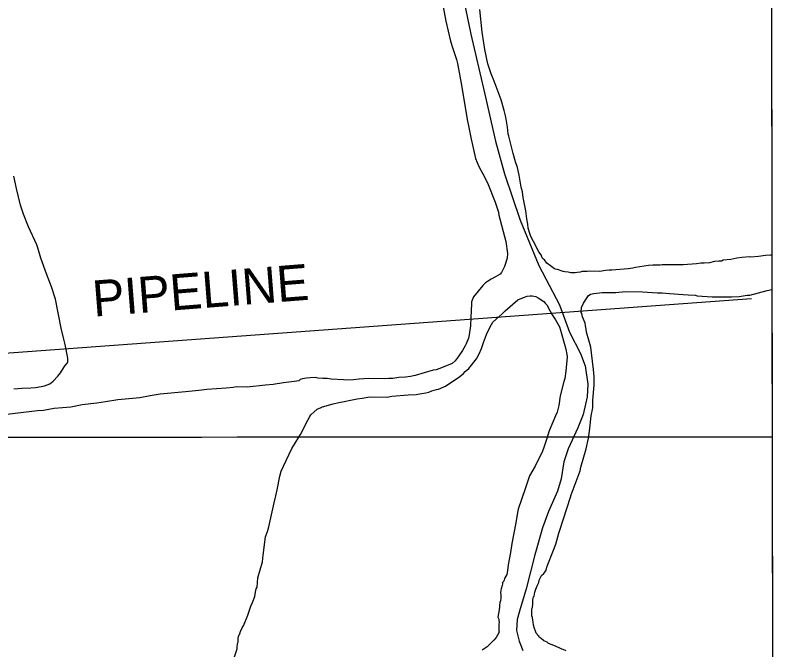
# Model space of a CAD drawing. Extents: x 3297772 to 3335630, y 634068 to 659439.
# Drawn here: x 3331686 to 3333452, y 654141 to 655604 of the extents above; entities that cross this region are included whole.
import ezdxf

# ---------------------------------------------------------------- set-up
doc = ezdxf.new("R2010")
doc.units = 0
for name, color, linetype in [('V-GRID-FRAM', 7, 'Continuous'), ('V-GRID-MAJR', 7, 'Continuous'), ('V-SITE-VEGE', 7, 'Continuous'), ('V-TOPO-SHOR', 7, 'Continuous'), ('V-UTIL-IDEN', 7, 'Continuous'), ('V-UTIL-LINE', 7, 'Continuous')]:
    doc.layers.add(name, color=color, linetype=linetype)

msp = doc.modelspace()

# ---------------------------------------------------------------- linework, layer by layer
at = {"layer": 'V-GRID-FRAM'}
msp.add_lwpolyline([(3301870.221, 657630.603), (3333425.538, 657662.73), (3333451.986, 639478.674), (3301880.801, 639446.531), (3301870.221, 657630.603)], dxfattribs=at)
at = {"layer": 'V-GRID-MAJR'}
msp.add_spline([(3301871.984, 654599.909), (3307131.646, 654603.3520000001), (3312391.307, 654607.559), (3317650.968, 654612.532), (3322910.628, 654618.27), (3328170.287, 654624.772), (3333429.9450000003, 654632.04), (3333429.946, 654632.04)], degree=3, dxfattribs=at)
at = {"layer": 'V-SITE-VEGE'}
for p, q in [((3333427.2330160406, 656497.3387944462), (3333429.3369402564, 655050.8068922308)), ((3332762.043, 655564.871), (3332756.688, 655617.125)), ((3332765.722, 655540.2089999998), (3332762.043, 655564.871)), ((3332767.534, 655525.4139999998), (3332765.722, 655540.2089999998)), ((3332775.059, 655491.8449999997), (3332767.534, 655525.4139999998)), ((3332782.698, 655469.112), (3332775.059, 655491.8449999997)), ((3332789.413, 655452.2980000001), (3332782.698, 655469.112)), ((3332805.6950000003, 655408.787), (3332789.413, 655452.2980000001)), ((3332812.328, 655384.094), (3332805.6950000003, 655408.787)), ((3332816.111, 655369.2809999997), (3332812.328, 655384.094)), ((3332819.799, 655345.604), (3332816.111, 655369.2809999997)), ((3332821.612, 655330.811), (3332819.799, 655345.604)), ((3332823.518, 655324.88), (3332821.612, 655330.811)), ((3332832.949, 655285.3819999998), (3332823.518, 655324.88)), ((3332838.653, 655265.625), (3332832.949, 655285.3819999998)), ((3332843.437, 655252.7699999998), (3332838.653, 655265.625)), ((3332847.1890000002, 655235.0009999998), (3332843.437, 655252.7699999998)), ((3332851.822, 655207.3740000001), (3332847.1890000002, 655235.0009999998)), ((3332854.66, 655196.509), (3332851.822, 655207.3740000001)), ((3332856.4930000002, 655183.6869999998), (3332854.66, 655196.509)), ((3332862.078, 655153.0959999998), (3332856.4930000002, 655183.6869999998)), ((3332864.833, 655134.3519999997), (3332862.078, 655153.0959999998)), ((3332866.68, 655122.513), (3332864.833, 655134.3519999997)), ((3332867.561, 655112.656), (3332866.68, 655122.513)), ((3332871.3740000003, 655100.7959999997), (3332867.561, 655112.656)), ((3332874.255, 655093.87), (3332871.3740000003, 655100.7959999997)), ((3332880.039, 655081.9889999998), (3332874.255, 655093.87)), ((3332892.591, 655058.216), (3332880.039, 655081.9889999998)), ((3332897.443, 655051.273), (3332892.591, 655058.216)), ((3332900.322, 655044.349), (3332897.443, 655051.273)), ((3333378.041, 655047.1629999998), (3333360.293, 655045.3789999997)), ((3333380.986, 655046.1449999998), (3333378.041, 655047.1629999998)), ((3333398.732, 655047.927), (3333380.986, 655046.1449999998)), ((3333414.5100000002, 655049.729), (3333398.732, 655047.927)), ((3333426.339, 655050.589), (3333414.5100000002, 655049.729)), ((3333429.3369402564, 655050.8068922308), (3333426.339, 655050.589)), ((3332903.247, 655041.361), (3332900.322, 655044.349)), ((3332905.207, 655040.353), (3332903.247, 655041.361)), ((3332911.031, 655032.415), (3332905.207, 655040.353)), ((3332918.847, 655026.4229999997), (3332911.031, 655032.415)), ((3333255.736, 655030.73), (3333225.176, 655028.1)), ((3333265.606, 655032.5959999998), (3333255.736, 655030.7299999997)), ((3333273.484, 655032.5139999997), (3333265.606, 655032.5959999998)), ((3333285.312, 655033.372), (3333273.484, 655032.5139999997)), ((3333297.161, 655036.2000000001), (3333285.312, 655033.372)), ((3333307.018, 655037.081), (3333297.161, 655036.2000000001)), ((3333312.929, 655037.017), (3333307.018, 655037.081)), ((3333316.8880000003, 655038.9459999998), (3333312.929, 655037.0169999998)), ((3333334.636, 655040.728), (3333316.8880000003, 655038.9459999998)), ((3333348.4560000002, 655043.536), (3333334.636, 655040.728)), ((3333360.293, 655045.379), (3333348.4560000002, 655043.536)), ((3332928.622, 655019.425), (3332918.847, 655026.4229999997)), ((3332930.582, 655018.419), (3332928.622, 655019.425)), ((3332935.495, 655017.383), (3332930.582, 655018.419)), ((3332948.256, 655013.31), (3332935.495, 655017.383)), ((3332952.184, 655012.279), (3332948.256, 655013.31)), ((3332960.052, 655011.212), (3332952.184, 655012.279)), ((3332987.637, 655011.905), (3332980.733, 655010.993)), ((3332992.572, 655012.8359999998), (3332987.637, 655011.9049999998)), ((3333003.404, 655012.7219999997), (3332992.572, 655012.8359999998)), ((3333009.323, 655013.6429999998), (3333003.404, 655012.7219999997)), ((3333032.9590000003, 655013.394), (3333009.323, 655013.6429999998)), ((3333045.784, 655015.229), (3333032.9590000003, 655013.394)), ((3333054.6580000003, 655016.117), (3333045.784, 655015.229)), ((3333060.566, 655016.056), (3333054.6580000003, 655016.117)), ((3333098.032, 655019.599), (3333060.566, 655016.056)), ((3333108.8740000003, 655020.4670000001), (3333098.032, 655019.599)), ((3333114.803, 655022.372), (3333108.8740000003, 655020.4670000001)), ((3333145.384, 655026.976), (3333114.803, 655022.372)), ((3333155.2430000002, 655027.856), (3333145.384, 655026.976)), ((3333171.988, 655027.678), (3333155.2430000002, 655027.856)), ((3333176.919, 655028.61), (3333171.988, 655027.678)), ((3333225.176, 655028.1), (3333176.919, 655028.6099999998)), ((3332965.951, 655010.166), (3332960.052, 655011.212)), ((3332975.799, 655010.059), (3332965.951, 655010.166)), ((3332980.733, 655010.993), (3332975.799, 655010.059)), ((3333006.3510000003, 654956.8030000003), (3333011.318, 654960.6900000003)), ((3333011.318, 654960.6900000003), (3333019.217, 654962.5760000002)), ((3333019.217, 654962.576), (3333037.948, 654964.348)), ((3333037.948, 654964.348), (3333069.473, 654964.9970000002)), ((3333069.473, 654964.9970000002), (3333091.159, 654966.7380000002)), ((3333091.159, 654966.738), (3333131.537, 654966.3120000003)), ((3333131.537, 654966.3120000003), (3333165.985, 654963.9750000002)), ((3333165.985, 654963.9750000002), (3333176.819, 654963.8610000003)), ((3333176.819, 654963.8610000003), (3333193.549, 654962.6970000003)), ((3333193.549, 654962.697), (3333225.041, 654960.395)), ((3333225.041, 654960.395), (3333236.85, 654959.283)), ((3333236.85, 654959.283), (3333252.597, 654958.132)), ((3333354.012, 654955.087), (3333372.7630000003, 654958.8290000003)), ((3333372.7630000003, 654958.8290000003), (3333378.674, 654958.7670000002)), ((3333378.674, 654958.7670000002), (3333418.182, 654969.1810000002)), ((3333418.182, 654969.1810000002), (3333429.452563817, 654971.3110771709)), ((3333429.452563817, 654971.3110771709), (3333430.9027316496, 653974.2627913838)), ((3332995.341, 654940.178), (3333003.355, 654952.8960000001)), ((3333003.355, 654952.8960000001), (3333006.3510000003, 654956.8030000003)), ((3333252.597, 654958.132), (3333257.5100000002, 654957.098)), ((3333257.5100000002, 654957.098), (3333291.957, 654954.7590000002)), ((3333291.957, 654954.7590000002), (3333336.274, 654954.2900000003)), ((3333336.274, 654954.29), (3333354.012, 654955.087)), ((3332990.187, 654918.563), (3332990.3140000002, 654930.3820000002)), ((3332990.3140000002, 654930.3820000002), (3332995.341, 654940.178)), ((3332991.151, 654916.582), (3332990.187, 654918.563)), ((3332993.037, 654908.6830000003), (3332991.151, 654916.582)), ((3332998.786, 654893.8500000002), (3332993.037, 654908.6830000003)), ((3332999.714, 654887.931), (3332998.786, 654893.8500000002)), ((3333001.598, 654880.0300000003), (3332999.714, 654887.931)), ((3333002.509, 654873.126), (3333001.598, 654880.0300000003)), ((3333007.234, 654854.362), (3333002.509, 654873.126)), ((3333011.992, 654838.554), (3333007.234, 654854.362)), ((3333013.827, 654825.7290000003), (3333011.992, 654838.554)), ((3333018.342, 654787.27), (3333013.827, 654825.7290000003)), ((3333020.134, 654770.507), (3333018.342, 654787.27)), ((3333019.926, 654750.811), (3333020.134, 654770.507)), ((3333016.606, 654716.3740000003), (3333019.926, 654750.811)), ((3333016.417, 654698.6470000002), (3333016.606, 654716.3740000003)), ((3333013.265, 654679.9670000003), (3333016.417, 654698.6470000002)), ((3333010.007, 654651.4380000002), (3333013.265, 654679.9670000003)), ((3333006.812, 654628.8200000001), (3333008.95, 654644.557)), ((3333008.95, 654644.557), (3333010.007, 654651.4380000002)), ((3333001.629, 654604.2520000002), (3333006.812, 654628.8200000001)), ((3332989.361, 654562.031), (3333001.629, 654604.2520000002)), ((3332978.173, 654528.6610000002), (3332987.299, 654553.1870000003)), ((3332987.299, 654553.1870000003), (3332989.361, 654562.031)), ((3332967.018, 654498.2460000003), (3332978.173, 654528.6610000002)), ((3332940.545, 654416.7780000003), (3332964.986, 654492.3600000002)), ((3332964.986, 654492.3600000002), (3332967.018, 654498.2460000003)), ((3332938.501, 654409.905), (3332940.545, 654416.7780000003)), ((3332931.3370000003, 654384.3750000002), (3332938.501, 654409.905)), ((3332924.255, 654366.721), (3332931.3370000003, 654384.3750000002)), ((3332913.108, 654337.291), (3332924.255, 654366.721)), ((3332906.028, 654319.638), (3332909.035, 654324.5300000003)), ((3332909.035, 654324.5300000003), (3332911.076, 654331.403)), ((3332911.076, 654331.403), (3332913.108, 654337.291)), ((3332893.187, 654300.9500000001), (3332898.117, 654311.7810000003)), ((3332898.117, 654311.7810000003), (3332904.0270000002, 654316.7050000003)), ((3332904.0270000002, 654316.705), (3332906.028, 654319.638)), ((3332885.3000000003, 654280.2710000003), (3332888.2600000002, 654288.15)), ((3332888.2600000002, 654288.15), (3332892.2, 654296.0260000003)), ((3332892.2, 654296.0260000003), (3332893.187, 654300.9500000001)), ((3332881.356, 654264.5120000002), (3332883.328, 654273.377)), ((3332883.328, 654273.377), (3332884.315, 654278.3010000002)), ((3332884.315, 654278.3010000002), (3332885.3000000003, 654280.2710000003)), ((3332878.394, 654243.8330000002), (3332878.399, 654255.652)), ((3332878.399, 654255.652), (3332880.369, 654262.5430000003)), ((3332880.369, 654262.5430000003), (3332881.356, 654264.5120000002)), ((3332876.414, 654219.212), (3332876.42, 654234.969)), ((3332876.42, 654234.969), (3332877.407, 654237.924)), ((3332877.407, 654241.865), (3332878.394, 654243.8330000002)), ((3332877.407, 654237.924), (3332877.407, 654241.865)), ((3332877.399, 654215.2720000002), (3332876.414, 654219.212)), ((3332878.38, 654208.378), (3332877.399, 654215.2720000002)), ((3332879.365, 654205.4230000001), (3332878.38, 654208.378)), ((3332880.346, 654197.5440000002), (3332879.365, 654205.4230000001)), ((3332882.3140000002, 654189.665), (3332880.346, 654197.5440000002)), ((3332884.2800000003, 654183.7550000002), (3332882.3140000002, 654189.665)), ((3332886.2490000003, 654178.8290000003), (3332884.2800000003, 654183.7550000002)), ((3332888.219, 654176.859), (3332886.2490000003, 654178.829)), ((3332890.187, 654173.904), (3332888.219, 654176.859)), ((3332892.157, 654171.934), (3332890.187, 654173.904)), ((3332893.14, 654169.964), (3332892.157, 654171.934)), ((3332898.063, 654167.0060000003), (3332893.14, 654169.9640000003)), ((3332903.97, 654161.094), (3332898.063, 654167.0060000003)), ((3332911.849, 654158.138), (3332903.97, 654161.094)), ((3332914.802, 654155.181), (3332911.849, 654158.138)), ((3332922.678, 654152.2240000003), (3332914.802, 654155.1810000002)), ((3332932.525, 654148.2810000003), (3332922.678, 654152.2240000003)), ((3332940.404, 654144.339), (3332932.525, 654148.2810000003)), ((3332945.327, 654142.367), (3332940.404, 654144.339)), ((3332948.282, 654141.382), (3332945.327, 654142.367)), ((3332955.176, 654138.424), (3332948.282, 654141.382))]:
    msp.add_line(p, q, dxfattribs=at)
for points in [[(3332671.649, 655623.206), (3332678.198, 655590.633)], [(3332678.198, 655590.633), (3332688.541, 655544.235), (3332694.271, 655527.429), (3332702.864, 655501.731), (3332704.738, 655492.845), (3332710.336, 655463.2390000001), (3332714.055, 655442.517), (3332727.006, 655363.583), (3332730.748, 655344.832), (3332736.376, 655318.179), (3332740.136, 655301.3960000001), (3332746.739, 655273.748), (3332754.419, 655254.951), (3332767.944, 655230.187), (3332775.644, 655213.36), (3332791.9590000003, 655172.806), (3332799.598, 655150.071), (3332800.509, 655143.167), (3332816.602, 655081.932), (3332820.25, 655054.3150000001), (3332819.15, 655043.493), (3332813.043, 655024.844), (3332806.004, 655011.128), (3332803.008, 655007.221), (3332792.1, 655000.442), (3332782.2, 654995.623), (3332774.2600000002, 654989.796), (3332769.304, 654986.894), (3332763.3340000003, 654981.049), (3332741.3850000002, 654954.6900000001), (3332737.3200000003, 654942.914), (3332737.269, 654937.988), (3332735.958, 654907.471), (3332734.7660000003, 654887.784), (3332733.677, 654877.947), (3332731.592, 654867.136), (3332730.525, 654859.265), (3332724.4790000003, 654846.527), (3332722.458, 654841.6240000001), (3332716.432, 654830.853), (3332706.426, 654816.185), (3332699.44, 654807.395), (3332692.475, 654800.576), (3332667.752, 654790.987), (3332655.879, 654786.188), (3332648.975, 654785.277), (3332607.4790000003, 654772.9130000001), (3332596.6240000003, 654771.058), (3332584.785, 654769.215), (3332570.003, 654768.385), (3332556.1950000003, 654766.562), (3332546.346, 654766.667), (3332536.487, 654765.786), (3332500.049, 654766.1730000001), (3332478.363, 654764.432), (3332465.5500000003, 654763.585), (3332447.813, 654762.7880000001), (3332441.904, 654762.849), (3332413.365, 654765.123), (3332404.512, 654766.202), (3332394.663, 654766.302), (3332382.856, 654767.414), (3332376.958, 654768.463), (3332365.129, 654767.603), (3332357.242, 654766.702), (3332347.383, 654765.821), (3332342.4390000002, 654763.904), (3332339.453, 654760.982), (3332333.532, 654760.06), (3332328.599, 654759.126), (3332303.947, 654756.435), (3332280.27, 654752.745), (3332262.522, 654750.963), (3332220.122, 654746.488), (3332194.518, 654746.758), (3332187.612, 654745.849), (3332171.836, 654744.045), (3332127.477, 654740.5750000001), (3332108.7460000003, 654738.804), (3332078.173, 654735.189), (3332020.008, 654729.895), (3331996.329, 654726.207), (3331972.642, 654721.533), (3331922.366, 654717.142), (3331893.753, 654712.522), (3331874.025, 654709.775), (3331839.505, 654705.2170000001), (3331813.846, 654700.566), (3331775.397, 654697.033), (3331750.725, 654692.37), (3331736.927, 654691.532), (3331653.107, 654681.587)], [(3331682.311, 654742.341), (3331701.042, 654744.112), (3331721.735, 654744.878), (3331732.575, 654745.7490000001), (3331745.4020000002, 654747.582), (3331753.303, 654749.468), (3331765.169, 654754.2660000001), (3331773.111, 654760.093), (3331784.0700000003, 654771.795), (3331790.063, 654779.61), (3331792.074, 654783.528), (3331801.073, 654796.238), (3331806.06, 654802.093), (3331807.065, 654804.053), (3331807.159, 654812.917), (3331800.6, 654844.503), (3331797.782, 654857.338), (3331791.148, 654882.031), (3331778.072, 654949.144), (3331769.511, 654977.797), (3331758.005, 655007.469), (3331744.605, 655044.054), (3331737.9620000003, 655067.762), (3331735.08, 655074.686), (3331715.823, 655116.256), (3331704.309, 655144.941), (3331697.634, 655165.6950000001), (3331688.193, 655204.208), (3331682.588, 655232.831)], [(3332242.81, 654285.303), (3332245.009, 654306.946), (3332255.2430000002, 654343.282), (3332257.381, 654359.019), (3332262.753, 654401.314), (3332267.8340000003, 654416.033), (3332269.889, 654423.889), (3332282.302, 654479.9), (3332286.4080000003, 654495.6140000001), (3332289.508, 654509.368), (3332295.751, 654540.822), (3332298.8310000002, 654552.608), (3332303.877, 654564.3740000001), (3332323.02, 654604.553), (3332331.034, 654617.2710000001), (3332339.058, 654630.9770000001), (3332343.06, 654636.8420000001), (3332360.156, 654670.149), (3332364.191, 654678.969), (3332367.187, 654682.877), (3332381.109, 654695.536), (3332390.9990000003, 654699.37), (3332393.975, 654701.309), (3332418.668, 654707.9400000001), (3332431.502, 654710.758), (3332443.348, 654713.589), (3332458.1550000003, 654716.386), (3332473.943, 654719.174), (3332484.798, 654721.027), (3332502.556, 654723.794), (3332542.932, 654723.366), (3332553.786, 654725.221), (3332591.251, 654728.765), (3332609.973, 654729.551), (3332621.811, 654731.394), (3332631.68, 654733.26), (3332638.594, 654735.156), (3332645.52, 654738.0380000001), (3332656.383, 654740.876), (3332661.319, 654741.81), (3332677.15, 654748.536), (3332709.8850000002, 654770.843), (3332718.825, 654777.642), (3332722.816, 654782.525), (3332730.7660000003, 654789.334), (3332748.734, 654811.797), (3332754.769, 654823.552), (3332759.8170000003, 654835.318), (3332764.8880000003, 654849.054), (3332771.98, 654867.691), (3332780.045, 654885.334), (3332786.071, 654896.105), (3332794.023, 654902.914), (3332807.9450000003, 654915.571), (3332814.911, 654922.393), (3332843.742, 654947.694), (3332856.608, 654953.4670000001), (3332865.502, 654956.328), (3332872.406, 654957.2390000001), (3332877.332, 654957.184), (3332885.188, 654955.134), (3332891.065, 654952.117), (3332903.786, 654944.104), (3332906.698, 654940.132), (3332910.595, 654936.1510000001), (3332918.316, 654921.295), (3332923.1580000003, 654913.365), (3332930.911, 654901.462), (3332939.607, 654885.613), (3332942.478, 654877.701), (3332951.95, 654842.1460000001), (3332954.822, 654834.237), (3332956.6550000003, 654821.414), (3332957.5870000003, 654816.476), (3332954.279, 654783.024), (3332952.131, 654766.302), (3332950.089, 654759.431), (3332941.8540000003, 654726.03), (3332938.671, 654704.395), (3332934.565, 654688.683), (3332930.5300000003, 654679.86), (3332916.379, 654645.5380000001), (3332909.2430000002, 654622.961), (3332904.1520000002, 654607.255), (3332901.105, 654598.424), (3332883.998, 654564.132), (3332870.954, 654541.616), (3332865.883, 654527.882), (3332860.794, 654512.176), (3332844.535, 654465.072), (3332843.466, 654457.206), (3332839.276, 654433.611), (3332829.9020000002, 654385.4500000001), (3332826.728, 654364.7980000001), (3332821.501, 654336.294), (3332820.381, 654323.5), (3332818.316, 654314.659)], [(3332818.316, 654314.659), (3332813.678, 654306.8640000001), (3332811.705, 654298.988), (3332808.75, 654296.032), (3332808.748, 654292.0920000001), (3332807.7630000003, 654289.139), (3332805.791, 654281.26), (3332804.804, 654278.307), (3332804.804, 654275.3520000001), (3332803.819, 654273.381), (3332804.8000000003, 654266.488), (3332804.798, 654259.594), (3332803.81, 654253.686), (3332802.823, 654249.746), (3332801.836, 654242.8520000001), (3332801.836, 654239.897), (3332800.849, 654233.003), (3332797.886, 654216.265), (3332799.8540000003, 654211.337), (3332799.8540000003, 654208.382), (3332800.841, 654204.444), (3332799.852, 654199.518), (3332799.845, 654184.746), (3332800.8310000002, 654181.7930000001), (3332799.843, 654179.821), (3332793.931, 654168.991), (3332789.003, 654163.082), (3332773.242, 654147.329), (3332761.419, 654139.457)], [(3332190.191, 654121.938), (3332197.09, 654142.617), (3332197.09, 654145.572), (3332198.082, 654155.419), (3332199.0670000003, 654158.3740000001), (3332199.071, 654167.24), (3332200.058, 654171.176), (3332203.998, 654180.04), (3332204.985, 654183.978), (3332208.928, 654190.872), (3332209.913, 654194.81), (3332211.881, 654195.7930000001), (3332221.742, 654220.412), (3332228.644, 654241.093), (3332232.586, 654249.954), (3332237.657, 654263.6900000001), (3332239.732, 654273.517), (3332240.799, 654281.385), (3332242.81, 654285.303)]]:
    msp.add_lwpolyline(points, dxfattribs=at)
at = {"layer": 'V-TOPO-SHOR'}
msp.add_lwpolyline([(3332715.4990000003, 655656.955), (3332735.794, 655560.373), (3332767.258, 655425.162), (3332792.63, 655313.333), (3332812.934, 655238.1), (3332849.491, 655131.35), (3332892.149, 655026.632), (3332939.894, 654936.1410000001), (3332963.2490000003, 654873.106), (3332988.646, 654824.304), (3332998.8000000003, 654795.837), (3333004.8850000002, 654753.138), (3333003.857, 654723.659), (3332994.694, 654683), (3332982.484, 654652.509), (3332960.1010000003, 654603.724), (3332949.927, 654574.247), (3332943.812, 654534.604), (3332935.669, 654506.143), (3332914.304, 654459.389), (3332901.076, 654421.782), (3332882.755, 654359.78), (3332863.411, 654281.512), (3332848.145, 654229.6730000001), (3332842.038, 654210.362), (3332841.012, 654184.949), (3332847.103, 654160.551), (3332855.326, 654138.848)], dxfattribs=at)
at = {"layer": 'V-UTIL-LINE'}
msp.add_lwpolyline([(3333382.298, 654950.366), (3326392.63, 654437.8690000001)], dxfattribs=at)

# ---------------------------------------------------------------- texts
at = {"layer": 'V-UTIL-IDEN'}
msp.add_text('PIPELINE', height=82.99983200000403, rotation=4.513983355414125, dxfattribs=at).set_placement((3331866.783228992, 654908.8544584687))

doc.saveas('drawing.dxf')
